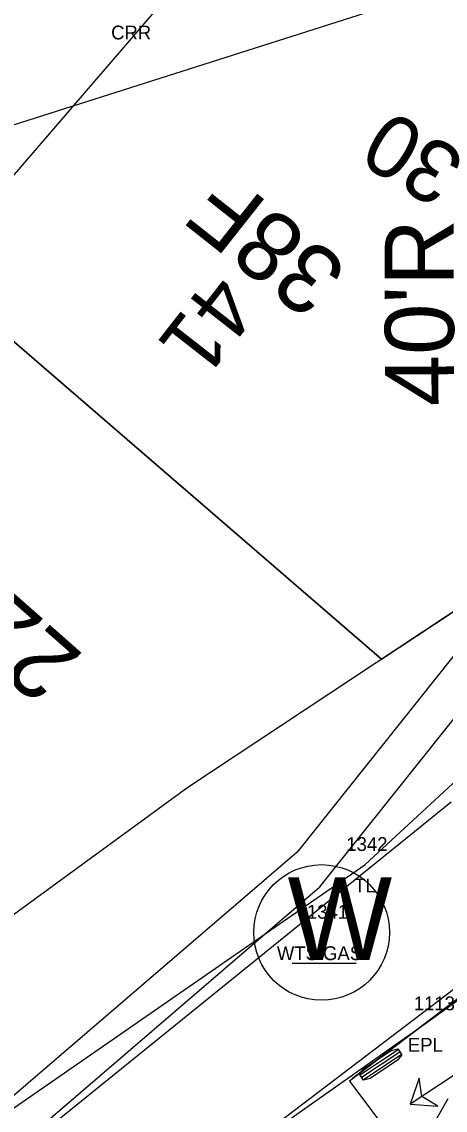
# Model space of a CAD drawing. Extents: x 1812113 to 1819860, y 1177290 to 1181185.
# Drawn here: x 1813713 to 1813743.6, y 1178588.3 to 1178667.1 of the extents above; entities that cross this region are included whole.
import ezdxf

# ---------------------------------------------------------------- set-up
doc = ezdxf.new("R2010")
doc.units = 0
for name, color, linetype in [('RD_EX_H2O_txCode', 7, 'Continuous'), ('RD_EX_Road', 7, 'Continuous'), ('RD_EX_Road_txCode', 7, 'Continuous'), ('RD_EX_RW', 7, 'Continuous'), ('RD_EX_UT', 7, 'Continuous'), ('RD_EX_UT_txCode', 7, 'Continuous'), ('RD_EX_VEG', 7, 'Continuous'), ('RD_EX_VEG_txCode', 7, 'Continuous'), ('RD_HC_Data', 7, 'Continuous'), ('RD_PD_ALT1_TrvlWay', 7, 'Continuous'), ('RD_PD_ALT3_TnTmp', 7, 'Continuous'), ('RD_PD_CstnLmt', 7, 'Continuous'), ('RD_PD_DR_ErosCtrl', 7, 'Continuous'), ('RD_PD_PatLn1', 7, 'Continuous'), ('RD_PD_RW', 7, 'Continuous'), ('RD_Sketch8', 7, 'Continuous'), ('RD_SMD_Locator', 7, 'Continuous'), ('ROW_Obtain_T3', 7, 'Continuous')]:
    doc.layers.add(name, color=color, linetype=linetype)

msp = doc.modelspace()

# ---------------------------------------------------------------- linework, layer by layer
at = {"layer": 'RD_EX_Road'}
for p, q in [((1813742.113, 1178594.538), (1813782.718, 1178623.8)), ((1813701.1, 1178565.691), (1813742.113, 1178594.538))]:
    msp.add_line(p, q, dxfattribs=at)
at = {"layer": 'RD_EX_RW'}
for p, q in [((1813782.499, 1178649.754), (1813724.979, 1178611.658)), ((1813724.979, 1178611.658), (1813565.452, 1178495.219))]:
    msp.add_line(p, q, dxfattribs=at)
at = {"layer": 'RD_EX_UT'}
msp.add_line((1813732.531, 1178598.957), (1813737.161, 1178598.957), dxfattribs=at)
msp.add_circle((1813734.66, 1178601.165), 4.908, dxfattribs=at)
at = {"layer": 'RD_EX_VEG'}
msp.add_lwpolyline([(1813569.577, 1178500.764), (1813635.352, 1178535.148), (1813737.799, 1178606.062), (1813775.895, 1178641.246), (1813752.752, 1178672.453), (1813690.463, 1178652.624), (1813708.106, 1178634.089), (1813540.707, 1178531.719)], dxfattribs=at)
at = {"layer": 'RD_HC_Data'}
for p, q in [((1813755.38, 1178705.862), (1813645.021, 1178577.927)), ((1813739.857, 1178582.268), (1813743.829, 1178589.147))]:
    msp.add_line(p, q, dxfattribs=at)
at = {"layer": 'RD_PD_ALT1_TrvlWay'}
msp.add_line((1813766.061, 1178613.679), (1813726.268, 1178583.405), dxfattribs=at)
at = {"layer": 'RD_PD_CstnLmt'}
for p, q in [((1813734.538, 1178604.47), (1813767.28, 1178645.585)), ((1813695.732, 1178571.156), (1813734.538, 1178604.47))]:
    msp.add_line(p, q, dxfattribs=at)
at = {"layer": 'RD_PD_DR_ErosCtrl'}
for p, q in [((1813758.886, 1178639.626), (1813732.882, 1178606.972)), ((1813732.882, 1178606.972), (1813693.964, 1178573.579))]:
    msp.add_line(p, q, dxfattribs=at)
at = {"layer": 'RD_PD_PatLn1'}
msp.add_line((1813696.765, 1178572.422), (1813744.04, 1178610.609), dxfattribs=at)
at = {"layer": 'RD_PD_RW'}
msp.add_line((1813739, 1178620.944), (1813706.392, 1178649.072), dxfattribs=at)
at = {"layer": 'RD_Sketch8'}
for p, q in [((1813782.266, 1178616.015), (1813741.076, 1178588.735)), ((1813765.212, 1178612.024), (1813736.669, 1178590.415)), ((1813737.43, 1178590.862), (1813740.21, 1178592.701)), ((1813737.545, 1178590.688), (1813740.325, 1178592.527)), ((1813737.66, 1178590.514), (1813740.44, 1178592.353)), ((1813736.669, 1178590.415), (1813741.497, 1178584.037))]:
    msp.add_line(p, q, dxfattribs=at)
msp.add_lwpolyline([(1813744.768, 1178596.547), (1813743.468, 1178595.563), (1813742.165, 1178594.576), (1813740.86, 1178593.588), (1813739.552, 1178592.598), (1813738.243, 1178591.607), (1813736.931, 1178590.614), (1813736.669, 1178590.415)], dxfattribs=at)
for points in [[(1813737.689, 1178590.471), (1813737.402, 1178590.905), (1813737.704, 1178591.293), (1813739.706, 1178592.617), (1813740.182, 1178592.744), (1813740.469, 1178592.31), (1813740.166, 1178591.922), (1813738.164, 1178590.598)], [(1813741.076, 1178588.735), (1813743.072, 1178588.596), (1813741.91, 1178589.287), (1813741.727, 1178590.626)], [(1813741.076, 1178588.735), (1813743.072, 1178588.596), (1813741.91, 1178589.287), (1813741.727, 1178590.626)]]:
    msp.add_lwpolyline(points, close=True, dxfattribs=at)
at = {"layer": 'RD_SMD_Locator'}
for centre in [(1813737.799, 1178606.062), (1813742.113, 1178594.538)]:
    msp.add_circle(centre, 0.001, dxfattribs=at)
at = {"layer": 'ROW_Obtain_T3'}
for p, q in [((1813706.392, 1178649.072), (1813739, 1178620.944)), ((1813739, 1178620.944), (1813782.499, 1178649.754))]:
    msp.add_line(p, q, dxfattribs=at)

# ---------------------------------------------------------------- texts
at = {"layer": 'RD_EX_H2O_txCode'}
msp.add_text('CRR', height=1, dxfattribs=at).set_placement((1813719.426, 1178665.781))
at = {"layer": 'RD_EX_Road_txCode'}
for s, p in [('1113', (1813741.334, 1178595.538)), ('EPL', (1813740.908, 1178592.538))]:
    msp.add_text(s, height=1, dxfattribs=at).set_placement(p)
at = {"layer": 'RD_EX_UT'}
msp.add_text('W', height=6, dxfattribs=at).set_placement((1813732.195, 1178599.164))
at = {"layer": 'RD_EX_UT_txCode'}
for s, p in [('1341', (1813733.597, 1178602.165)), ('WTS GAS', (1813731.423, 1178599.165))]:
    msp.add_text(s, height=1, dxfattribs=at).set_placement(p)
at = {"layer": 'RD_EX_VEG_txCode'}
for s, p in [('1342', (1813736.452, 1178607.062)), ('TL', (1813737.027, 1178604.062))]:
    msp.add_text(s, height=1, dxfattribs=at).set_placement(p)
at = {"layer": 'RD_PD_ALT3_TnTmp'}
msp.add_text("40'R", height=5, rotation=90.14619, dxfattribs=at).set_placement((1813744.255, 1178639.241))
at = {"layer": 'RD_PD_CstnLmt'}
for s, rotation, p in [('38F', 141.63075, (1813736.752, 1178649.27)), ('22F', 138.62848, (1813717.522, 1178621.193))]:
    msp.add_text(s, height=5, rotation=rotation, dxfattribs=at).set_placement(p)
at = {"layer": 'RD_PD_DR_ErosCtrl'}
for s, rotation, p in [('30', 148.54433, (1813745.267, 1178657.299)), ('41', 231.98411, (1813726.795, 1178649.08))]:
    msp.add_text(s, height=4.5, rotation=rotation, dxfattribs=at).set_placement(p)

doc.saveas('drawing.dxf')
